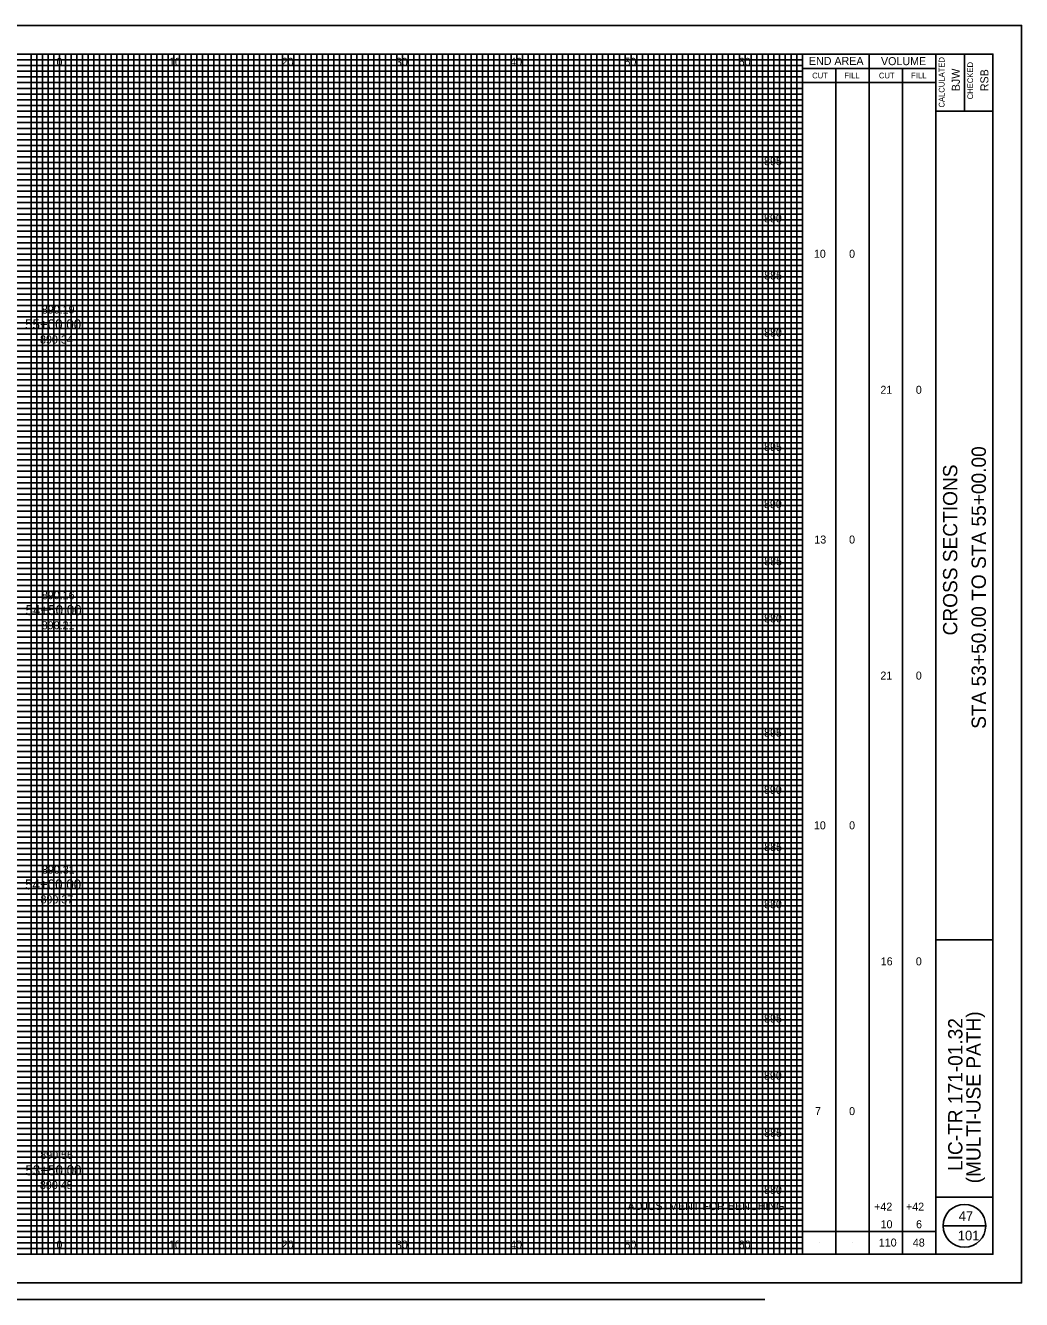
# Model space of a CAD drawing. Extents: x -10 to 160, y -2 to 2522.
# Drawn here: x 72.8 to 160, y 2181 to 2292.5 of the extents above; entities that cross this region are included whole.
import ezdxf

# ---------------------------------------------------------------- set-up
doc = ezdxf.new("R2010")
doc.units = 0
for name, color, linetype in [('GK_Cells', 7, 'Continuous'), ('GK_Patterns', 7, 'Continuous'), ('TX_P_10', 7, 'Continuous'), ('TX_X_10', 7, 'Continuous'), ('XS_P_Finished_Grade_Seeded', 7, 'Continuous'), ('XS_P_Pavt_Surface', 7, 'Continuous'), ('XS_P_Subgrade', 7, 'Continuous'), ('XS_X_Ground_Line', 7, 'Continuous')]:
    doc.layers.add(name, color=color, linetype=linetype)

msp = doc.modelspace()

# ---------------------------------------------------------------- linework, layer by layer
at = {"layer": 'GK_Cells'}
msp.add_lwpolyline([(-10, 2182.5), (160, 2182.5), (160, 2292.5), (-10, 2292.5)], close=True, dxfattribs=at)
at = {"layer": 'TX_P_10'}
for p, q in [((140.83, 2185), (140.83, 2290)), ((146.67, 2185), (146.67, 2290)), ((140.83, 2288.75), (152.5, 2288.75)), ((143.75, 2185), (143.75, 2288.75)), ((149.58, 2185), (149.58, 2288.75)), ((140.83, 2287.5), (152.5, 2287.5)), ((140.83, 2187), (152.5, 2187)), ((153.12, 2187.5), (156.88, 2187.5)), ((142.29, 2186), (142.29, 2186)), ((145.21, 2186), (145.21, 2186)), ((148.12, 2186), (148.12, 2186)), ((151.04, 2186), (151.04, 2186))]:
    msp.add_line(p, q, dxfattribs=at)
msp.add_circle((155, 2187.5), 1.87, dxfattribs=at)
at = {"layer": 'TX_X_10'}
for p, q in [((75.83, 2185), (75.83, 2290)), ((80.83, 2185), (80.83, 2290)), ((85.83, 2185), (85.83, 2290)), ((90.83, 2185), (90.83, 2290)), ((95.83, 2185), (95.83, 2290)), ((100.83, 2185), (100.83, 2290)), ((105.83, 2185), (105.83, 2290)), ((110.83, 2185), (110.83, 2290)), ((115.83, 2185), (115.83, 2290)), ((120.83, 2185), (120.83, 2290)), ((125.83, 2185), (125.83, 2290)), ((130.83, 2185), (130.83, 2290)), ((135.83, 2185), (135.83, 2290)), ((5.83, 2285), (140.83, 2285)), ((5.83, 2280), (140.83, 2280)), ((5.83, 2275), (140.83, 2275)), ((5.83, 2270), (140.83, 2270)), ((5.83, 2265), (140.83, 2265)), ((5.83, 2260), (140.83, 2260)), ((5.83, 2255), (140.83, 2255)), ((5.83, 2250), (140.83, 2250)), ((5.83, 2245), (140.83, 2245)), ((5.83, 2240), (140.83, 2240)), ((5.83, 2235), (140.83, 2235)), ((5.83, 2230), (140.83, 2230)), ((5.83, 2225), (140.83, 2225)), ((5.83, 2220), (140.83, 2220)), ((5.83, 2215), (140.83, 2215)), ((5.83, 2210), (140.83, 2210)), ((5.83, 2205), (140.83, 2205)), ((5.83, 2200), (140.83, 2200)), ((5.83, 2195), (140.83, 2195)), ((5.83, 2190), (140.83, 2190)), ((2.53, 2181.05), (137.53, 2181.05))]:
    msp.add_line(p, q, dxfattribs=at)
at = {"layer": 'XS_P_Pavt_Surface'}
for p, q in [((152.5, 2185), (152.5, 2290)), ((155, 2290), (155, 2285)), ((152.5, 2285), (157.5, 2285)), ((152.5, 2212.5), (157.5, 2212.5)), ((152.5, 2190), (157.5, 2190))]:
    msp.add_line(p, q, dxfattribs=at)
msp.add_lwpolyline([(0, 2290), (157.5, 2290), (157.5, 2185), (0, 2185)], close=True, dxfattribs=at)
at = {"layer": 'XS_X_Ground_Line'}
for p, q in [((5.83, 2289.5), (140.83, 2289.5)), ((73.33, 2185), (73.33, 2290)), ((73.83, 2185), (73.83, 2290)), ((74.33, 2185), (74.33, 2290)), ((74.83, 2185), (74.83, 2290)), ((75.33, 2185), (75.33, 2290)), ((76.33, 2185), (76.33, 2290)), ((76.83, 2185), (76.83, 2290)), ((77.33, 2185), (77.33, 2290)), ((77.83, 2185), (77.83, 2290)), ((78.33, 2185), (78.33, 2290)), ((78.83, 2185), (78.83, 2290)), ((79.33, 2185), (79.33, 2290)), ((79.83, 2185), (79.83, 2290)), ((80.33, 2185), (80.33, 2290)), ((81.33, 2185), (81.33, 2290)), ((81.83, 2185), (81.83, 2290)), ((82.33, 2185), (82.33, 2290)), ((82.83, 2185), (82.83, 2290)), ((83.33, 2185), (83.33, 2290)), ((83.83, 2185), (83.83, 2290)), ((84.33, 2185), (84.33, 2290)), ((84.83, 2185), (84.83, 2290)), ((85.33, 2185), (85.33, 2290)), ((86.33, 2185), (86.33, 2290)), ((86.83, 2185), (86.83, 2290)), ((87.33, 2185), (87.33, 2290)), ((87.83, 2185), (87.83, 2290)), ((88.33, 2185), (88.33, 2290)), ((88.83, 2185), (88.83, 2290)), ((89.33, 2185), (89.33, 2290)), ((89.83, 2185), (89.83, 2290)), ((90.33, 2185), (90.33, 2290)), ((91.33, 2185), (91.33, 2290)), ((91.83, 2185), (91.83, 2290)), ((92.33, 2185), (92.33, 2290)), ((92.83, 2185), (92.83, 2290)), ((93.33, 2185), (93.33, 2290)), ((93.83, 2185), (93.83, 2290)), ((94.33, 2185), (94.33, 2290)), ((94.83, 2185), (94.83, 2290)), ((95.33, 2185), (95.33, 2290)), ((96.33, 2185), (96.33, 2290)), ((96.83, 2185), (96.83, 2290)), ((97.33, 2185), (97.33, 2290)), ((97.83, 2185), (97.83, 2290)), ((98.33, 2185), (98.33, 2290)), ((98.83, 2185), (98.83, 2290)), ((99.33, 2185), (99.33, 2290)), ((99.83, 2185), (99.83, 2290)), ((100.33, 2185), (100.33, 2290)), ((101.33, 2185), (101.33, 2290)), ((101.83, 2185), (101.83, 2290)), ((102.33, 2185), (102.33, 2290)), ((102.83, 2185), (102.83, 2290)), ((103.33, 2185), (103.33, 2290)), ((103.83, 2185), (103.83, 2290)), ((104.33, 2185), (104.33, 2290)), ((104.83, 2185), (104.83, 2290)), ((105.33, 2185), (105.33, 2290)), ((106.33, 2185), (106.33, 2290)), ((106.83, 2185), (106.83, 2290)), ((107.33, 2185), (107.33, 2290)), ((107.83, 2185), (107.83, 2290)), ((108.33, 2185), (108.33, 2290)), ((108.83, 2185), (108.83, 2290)), ((109.33, 2185), (109.33, 2290)), ((109.83, 2185), (109.83, 2290)), ((110.33, 2185), (110.33, 2290)), ((111.33, 2185), (111.33, 2290)), ((111.83, 2185), (111.83, 2290)), ((112.33, 2185), (112.33, 2290)), ((112.83, 2185), (112.83, 2290)), ((113.33, 2185), (113.33, 2290)), ((113.83, 2185), (113.83, 2290)), ((114.33, 2185), (114.33, 2290)), ((114.83, 2185), (114.83, 2290)), ((115.33, 2185), (115.33, 2290)), ((116.33, 2185), (116.33, 2290)), ((116.83, 2185), (116.83, 2290)), ((117.33, 2185), (117.33, 2290)), ((117.83, 2185), (117.83, 2290)), ((118.33, 2185), (118.33, 2290)), ((118.83, 2185), (118.83, 2290)), ((119.33, 2185), (119.33, 2290)), ((119.83, 2185), (119.83, 2290)), ((120.33, 2185), (120.33, 2290)), ((121.33, 2185), (121.33, 2290)), ((121.83, 2185), (121.83, 2290)), ((122.33, 2185), (122.33, 2290)), ((122.83, 2185), (122.83, 2290)), ((123.33, 2185), (123.33, 2290)), ((123.83, 2185), (123.83, 2290)), ((124.33, 2185), (124.33, 2290)), ((124.83, 2185), (124.83, 2290)), ((125.33, 2185), (125.33, 2290)), ((126.33, 2185), (126.33, 2290)), ((126.83, 2185), (126.83, 2290)), ((127.33, 2185), (127.33, 2290)), ((127.83, 2185), (127.83, 2290)), ((128.33, 2185), (128.33, 2290)), ((128.83, 2185), (128.83, 2290)), ((129.33, 2185), (129.33, 2290)), ((129.83, 2185), (129.83, 2290)), ((130.33, 2185), (130.33, 2290)), ((131.33, 2185), (131.33, 2290)), ((131.83, 2185), (131.83, 2290)), ((132.33, 2185), (132.33, 2290)), ((132.83, 2185), (132.83, 2290)), ((133.33, 2185), (133.33, 2290)), ((133.83, 2185), (133.83, 2290)), ((134.33, 2185), (134.33, 2290)), ((134.83, 2185), (134.83, 2290)), ((135.33, 2185), (135.33, 2290)), ((136.33, 2185), (136.33, 2290)), ((136.83, 2185), (136.83, 2290)), ((137.33, 2185), (137.33, 2290)), ((137.83, 2185), (137.83, 2290)), ((138.33, 2185), (138.33, 2290)), ((138.83, 2185), (138.83, 2290)), ((139.33, 2185), (139.33, 2290)), ((139.83, 2185), (139.83, 2290)), ((140.33, 2185), (140.33, 2290)), ((5.83, 2289), (140.83, 2289)), ((5.83, 2288.5), (140.83, 2288.5)), ((5.83, 2288), (140.83, 2288)), ((5.83, 2287.5), (140.83, 2287.5)), ((5.83, 2287), (140.83, 2287)), ((5.83, 2286.5), (140.83, 2286.5)), ((5.83, 2286), (140.83, 2286)), ((5.83, 2285.5), (140.83, 2285.5)), ((5.83, 2284.5), (140.83, 2284.5)), ((5.83, 2284), (140.83, 2284)), ((5.83, 2283.5), (140.83, 2283.5)), ((5.83, 2283), (140.83, 2283)), ((5.83, 2282.5), (140.83, 2282.5)), ((5.83, 2282), (140.83, 2282)), ((5.83, 2281.5), (140.83, 2281.5)), ((5.83, 2281), (140.83, 2281)), ((5.83, 2280.5), (140.83, 2280.5)), ((5.83, 2279.5), (140.83, 2279.5)), ((5.83, 2279), (140.83, 2279)), ((5.83, 2278.5), (140.83, 2278.5)), ((5.83, 2278), (140.83, 2278)), ((5.83, 2277.5), (140.83, 2277.5)), ((5.83, 2277), (140.83, 2277)), ((5.83, 2276.5), (140.83, 2276.5)), ((5.83, 2276), (140.83, 2276)), ((5.83, 2275.5), (140.83, 2275.5)), ((5.83, 2274.5), (140.83, 2274.5)), ((5.83, 2274), (140.83, 2274)), ((5.83, 2273.5), (140.83, 2273.5)), ((5.83, 2273), (140.83, 2273)), ((5.83, 2272.5), (140.83, 2272.5)), ((5.83, 2272), (140.83, 2272)), ((5.83, 2271.5), (140.83, 2271.5)), ((5.83, 2271), (140.83, 2271)), ((5.83, 2270.5), (140.83, 2270.5)), ((5.83, 2269.5), (140.83, 2269.5)), ((5.83, 2269), (140.83, 2269)), ((5.83, 2268.5), (140.83, 2268.5)), ((5.83, 2268), (140.83, 2268)), ((5.83, 2267.5), (140.83, 2267.5)), ((5.83, 2267), (140.83, 2267)), ((5.83, 2266.5), (140.83, 2266.5)), ((5.83, 2266), (140.83, 2266)), ((5.83, 2265.5), (140.83, 2265.5)), ((5.83, 2264.5), (140.83, 2264.5)), ((5.83, 2264), (140.83, 2264)), ((5.83, 2263.5), (140.83, 2263.5)), ((5.83, 2263), (140.83, 2263)), ((5.83, 2262.5), (140.83, 2262.5)), ((5.83, 2262), (140.83, 2262)), ((5.83, 2261.5), (140.83, 2261.5)), ((5.83, 2261), (140.83, 2261)), ((5.83, 2260.5), (140.83, 2260.5)), ((5.83, 2259.5), (140.83, 2259.5)), ((5.83, 2259), (140.83, 2259)), ((5.83, 2258.5), (140.83, 2258.5)), ((5.83, 2258), (140.83, 2258)), ((5.83, 2257.5), (140.83, 2257.5)), ((5.83, 2257), (140.83, 2257)), ((5.83, 2256.5), (140.83, 2256.5)), ((5.83, 2256), (140.83, 2256)), ((5.83, 2255.5), (140.83, 2255.5)), ((5.83, 2254.5), (140.83, 2254.5)), ((5.83, 2254), (140.83, 2254)), ((5.83, 2253.5), (140.83, 2253.5)), ((5.83, 2253), (140.83, 2253)), ((5.83, 2252.5), (140.83, 2252.5)), ((5.83, 2252), (140.83, 2252)), ((5.83, 2251.5), (140.83, 2251.5)), ((5.83, 2251), (140.83, 2251)), ((5.83, 2250.5), (140.83, 2250.5)), ((5.83, 2249.5), (140.83, 2249.5)), ((5.83, 2249), (140.83, 2249)), ((5.83, 2248.5), (140.83, 2248.5)), ((5.83, 2248), (140.83, 2248)), ((5.83, 2247.5), (140.83, 2247.5)), ((5.83, 2247), (140.83, 2247)), ((5.83, 2246.5), (140.83, 2246.5)), ((5.83, 2246), (140.83, 2246)), ((5.83, 2245.5), (140.83, 2245.5)), ((5.83, 2244.5), (140.83, 2244.5)), ((5.83, 2244), (140.83, 2244)), ((5.83, 2243.5), (140.83, 2243.5)), ((5.83, 2243), (140.83, 2243)), ((5.83, 2242.5), (140.83, 2242.5)), ((5.83, 2242), (140.83, 2242)), ((5.83, 2241.5), (140.83, 2241.5)), ((5.83, 2241), (140.83, 2241)), ((5.83, 2240.5), (140.83, 2240.5)), ((5.83, 2239.5), (140.83, 2239.5)), ((5.83, 2239), (140.83, 2239)), ((5.83, 2238.5), (140.83, 2238.5)), ((5.83, 2238), (140.83, 2238)), ((5.83, 2237.5), (140.83, 2237.5)), ((5.83, 2237), (140.83, 2237)), ((5.83, 2236.5), (140.83, 2236.5)), ((5.83, 2236), (140.83, 2236)), ((5.83, 2235.5), (140.83, 2235.5)), ((5.83, 2234.5), (140.83, 2234.5)), ((5.83, 2234), (140.83, 2234)), ((5.83, 2233.5), (140.83, 2233.5)), ((5.83, 2233), (140.83, 2233)), ((5.83, 2232.5), (140.83, 2232.5)), ((5.83, 2232), (140.83, 2232)), ((5.83, 2231.5), (140.83, 2231.5)), ((5.83, 2231), (140.83, 2231)), ((5.83, 2230.5), (140.83, 2230.5)), ((5.83, 2229.5), (140.83, 2229.5)), ((5.83, 2229), (140.83, 2229)), ((5.83, 2228.5), (140.83, 2228.5)), ((5.83, 2228), (140.83, 2228)), ((5.83, 2227.5), (140.83, 2227.5)), ((5.83, 2227), (140.83, 2227)), ((5.83, 2226.5), (140.83, 2226.5)), ((5.83, 2226), (140.83, 2226)), ((5.83, 2225.5), (140.83, 2225.5)), ((5.83, 2224.5), (140.83, 2224.5)), ((5.83, 2224), (140.83, 2224)), ((5.83, 2223.5), (140.83, 2223.5)), ((5.83, 2223), (140.83, 2223)), ((5.83, 2222.5), (140.83, 2222.5)), ((5.83, 2222), (140.83, 2222)), ((5.83, 2221.5), (140.83, 2221.5)), ((5.83, 2221), (140.83, 2221)), ((5.83, 2220.5), (140.83, 2220.5)), ((5.83, 2219.5), (140.83, 2219.5)), ((5.83, 2219), (140.83, 2219)), ((5.83, 2218.5), (140.83, 2218.5)), ((5.83, 2218), (140.83, 2218)), ((5.83, 2217.5), (140.83, 2217.5)), ((5.83, 2217), (140.83, 2217)), ((5.83, 2216.5), (140.83, 2216.5)), ((5.83, 2216), (140.83, 2216)), ((5.83, 2215.5), (140.83, 2215.5)), ((5.83, 2214.5), (140.83, 2214.5)), ((5.83, 2214), (140.83, 2214)), ((5.83, 2213.5), (140.83, 2213.5)), ((5.83, 2213), (140.83, 2213)), ((5.83, 2212.5), (140.83, 2212.5)), ((5.83, 2212), (140.83, 2212)), ((5.83, 2211.5), (140.83, 2211.5)), ((5.83, 2211), (140.83, 2211)), ((5.83, 2210.5), (140.83, 2210.5)), ((5.83, 2209.5), (140.83, 2209.5)), ((5.83, 2209), (140.83, 2209)), ((5.83, 2208.5), (140.83, 2208.5)), ((5.83, 2208), (140.83, 2208)), ((5.83, 2207.5), (140.83, 2207.5)), ((5.83, 2207), (140.83, 2207)), ((5.83, 2206.5), (140.83, 2206.5)), ((5.83, 2206), (140.83, 2206)), ((5.83, 2205.5), (140.83, 2205.5)), ((5.83, 2204.5), (140.83, 2204.5)), ((5.83, 2204), (140.83, 2204)), ((5.83, 2203.5), (140.83, 2203.5)), ((5.83, 2203), (140.83, 2203)), ((5.83, 2202.5), (140.83, 2202.5)), ((5.83, 2202), (140.83, 2202)), ((5.83, 2201.5), (140.83, 2201.5)), ((5.83, 2201), (140.83, 2201)), ((5.83, 2200.5), (140.83, 2200.5)), ((5.83, 2199.5), (140.83, 2199.5)), ((5.83, 2199), (140.83, 2199)), ((5.83, 2198.5), (140.83, 2198.5)), ((5.83, 2198), (140.83, 2198)), ((5.83, 2197.5), (140.83, 2197.5)), ((5.83, 2197), (140.83, 2197)), ((5.83, 2196.5), (140.83, 2196.5)), ((5.83, 2196), (140.83, 2196)), ((5.83, 2195.5), (140.83, 2195.5)), ((5.83, 2194.5), (140.83, 2194.5)), ((5.83, 2194), (140.83, 2194)), ((5.83, 2193.5), (140.83, 2193.5)), ((5.83, 2193), (140.83, 2193)), ((5.83, 2192.5), (140.83, 2192.5)), ((5.83, 2192), (140.83, 2192)), ((5.83, 2191.5), (140.83, 2191.5)), ((5.83, 2191), (140.83, 2191)), ((5.83, 2190.5), (140.83, 2190.5)), ((5.83, 2189.5), (140.83, 2189.5)), ((5.83, 2189), (140.83, 2189)), ((5.83, 2188.5), (140.83, 2188.5)), ((5.83, 2188), (140.83, 2188)), ((5.83, 2187.5), (140.83, 2187.5)), ((5.83, 2187), (140.83, 2187)), ((5.83, 2186.5), (140.83, 2186.5)), ((5.83, 2186), (140.83, 2186)), ((5.83, 2185.5), (140.83, 2185.5))]:
    msp.add_line(p, q, dxfattribs=at)

# ---------------------------------------------------------------- texts
at = {"layer": 'GK_Patterns'}
for s, height, p in [('0', 0.7, (75.55, 2288.97)), ('0', 0.7, (75.55, 2288.97)), ('10', 0.7, (85.39, 2288.97)), ('20', 0.7, (95.26, 2288.97)), ('30', 0.7, (105.25, 2288.97)), ('40', 0.7, (115.25, 2288.97)), ('50', 0.7, (125.25, 2288.97)), ('60', 0.7, (135.25, 2288.97)), ('895', 0.7, (137.47, 2280.28)), ('890', 0.7, (137.46, 2275.28)), ('10', 0.7, (141.83, 2272.18)), ('0', 0.7, (144.91, 2272.18)), ('885', 0.7, (137.48, 2270.28)), ('55+00.00', 0.875, (72.8, 2265.92)), ('880', 0.7, (137.47, 2265.28)), ('21', 0.7, (147.65, 2260.28)), ('0', 0.7, (150.75, 2260.28)), ('895', 0.7, (137.47, 2255.28)), ('890', 0.7, (137.46, 2250.28)), ('13', 0.7, (141.87, 2247.18)), ('0', 0.7, (144.91, 2247.18)), ('885', 0.7, (137.48, 2245.28)), ('54+50.00', 0.875, (72.84, 2240.92)), ('880', 0.7, (137.47, 2240.28)), ('21', 0.7, (147.65, 2235.28)), ('0', 0.7, (150.75, 2235.28)), ('895', 0.7, (137.47, 2230.28)), ('890', 0.7, (137.46, 2225.28)), ('10', 0.7, (141.83, 2222.18)), ('0', 0.7, (144.91, 2222.18)), ('885', 0.7, (137.48, 2220.28)), ('54+00.00', 0.875, (72.8, 2216.92)), ('880', 0.7, (137.47, 2215.28)), ('16', 0.7, (147.68, 2210.28)), ('0', 0.7, (150.75, 2210.28)), ('895', 0.7, (137.47, 2205.28)), ('890', 0.7, (137.46, 2200.28)), ('7', 0.7, (141.93, 2197.18)), ('0', 0.7, (144.91, 2197.18)), ('885', 0.7, (137.48, 2195.28)), ('53+50.00', 0.875, (72.83, 2191.92)), ('880', 0.7, (137.47, 2190.28)), ('ADJUSTMENT FOR BENCHING', 0.7, (125.52, 2188.87)), ('+42', 0.7, (147.1, 2188.82)), ('+42', 0.7, (149.89, 2188.82)), ('10', 0.7, (147.67, 2187.28)), ('6', 0.7, (150.77, 2187.28)), ('0', 0.7, (75.55, 2185.5)), ('0', 0.7, (75.55, 2185.5)), ('10', 0.7, (85.39, 2185.5)), ('20', 0.7, (95.26, 2185.5)), ('30', 0.7, (105.25, 2185.5)), ('40', 0.7, (115.25, 2185.5)), ('50', 0.7, (125.25, 2185.5)), ('60', 0.7, (135.25, 2185.5)), ('110', 0.7, (147.51, 2185.68)), ('48', 0.7, (150.49, 2185.68))]:
    msp.add_text(s, height=height, dxfattribs=at).set_placement(p)
at = {"layer": 'TX_P_10'}
for s, height, p in [('END AREA', 0.7, (141.39, 2289.05)), ('VOLUME', 0.7, (147.7, 2289.03)), ('CUT', 0.5, (141.68, 2287.87)), ('FILL', 0.5, (144.5, 2287.87)), ('CUT', 0.5, (147.52, 2287.87)), ('FILL', 0.5, (150.34, 2287.87)), ('47', 0.85, (154.5, 2187.92)), ('101', 0.85, (154.42, 2186.22))]:
    msp.add_text(s, height=height, dxfattribs=at).set_placement(p)
for s, height, p in [('CALCULATED', 0.5, (153.26, 2285.32)), ('CHECKED', 0.5, (155.76, 2286.04)), ('BJW', 0.7, (154.6, 2286.75)), ('RSB', 0.7, (157.1, 2286.75)), ('STA 53+50.00 TO STA 55+00.00', 1.25, (156.88, 2230.97)), ('CROSS SECTIONS', 1.25, (154.38, 2239.14)), ('(MULTI-USE PATH)', 1.25, (156.42, 2191.21)), ('LIC-TR 171-01.32', 1.25, (154.83, 2192.29))]:
    msp.add_text(s, height=height, rotation=90, dxfattribs=at).set_placement(p)
at = {"layer": 'XS_P_Finished_Grade_Seeded'}
for s, p in [('890.34', (74.11, 2264.68)), ('890.21', (74.26, 2239.68)), ('890.37', (74.15, 2215.7)), ('890.45', (74.1, 2190.71))]:
    msp.add_text(s, height=0.7, dxfattribs=at).set_placement(p)
at = {"layer": 'XS_P_Subgrade'}
for s, p in [('890.19', (74.27, 2267.3)), ('890.16', (74.27, 2242.31)), ('890.31', (74.28, 2218.3)), ('890.56', (74.13, 2193.35))]:
    msp.add_text(s, height=0.7, dxfattribs=at).set_placement(p)

doc.saveas('drawing.dxf')
